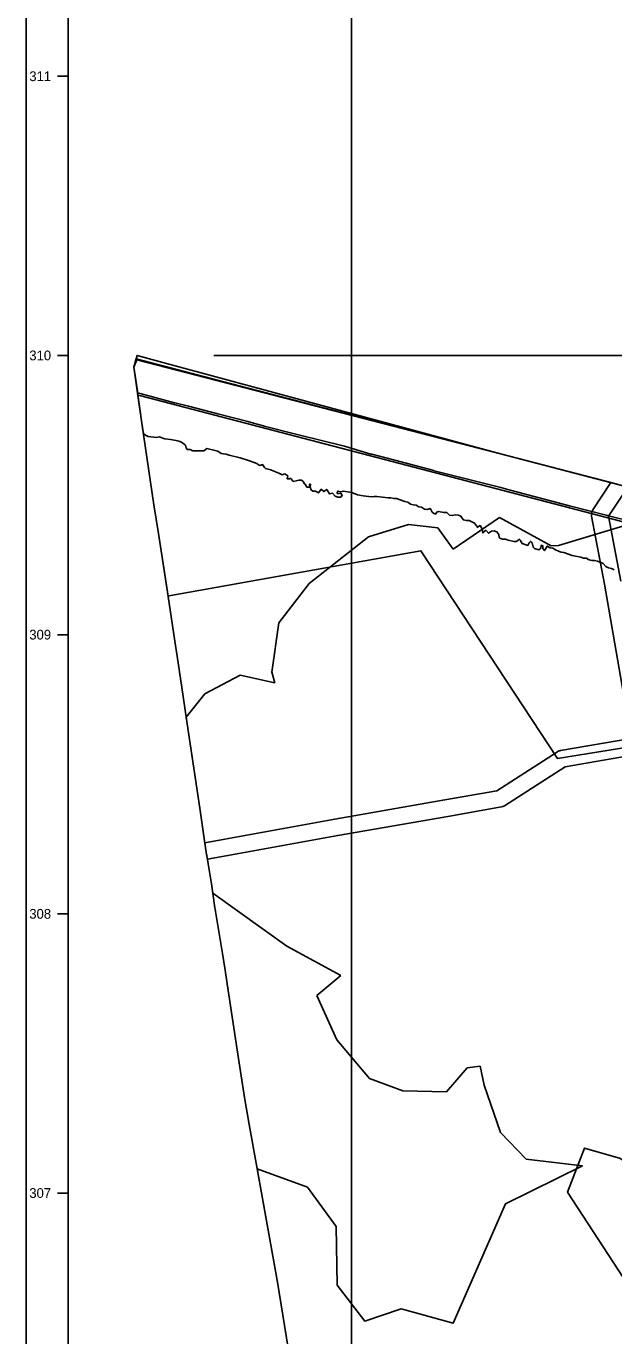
# Model space of a CAD drawing. Extents: x 468834 to 503362, y 294936 to 320859.
# Drawn here: x 468834 to 470940, y 306489 to 311179 of the extents above; entities that cross this region are included whole.
import ezdxf

# ---------------------------------------------------------------- set-up
doc = ezdxf.new("R2010")
doc.units = 0
for name, color, linetype in [('1020108_TIN18_Kemeru_nacionala_parka_teritorija', 7, 'Continuous'), ('1020109_TIN19_Auto satiksmes radīto trokšņu robežlieluma pārsnieguma teritorija', 7, 'Continuous'), ('1020700_TIN7_nacionalas_un_vietejas_nozimes_infrastrukturas_attistibas_teritorijas', 7, 'Continuous'), ('7311080102_vides un dabas resursu aizsardzības aizsargjoslas teritorija ap purvu ar platību lielāku par 100 hektāriem', 7, 'Continuous'), ('7312030301_ekspluatācijas aizsargjoslas teritorija gar valsts galvenajiem autoceļiem lauku apvidos', 7, 'Continuous'), ('7312050102_ekspluatācijas aizsargjoslas teritorija gar elektrisko tīklu gaisvadu līniju ārpus pilsētām un ciemiem ar nominālo spriegumu 110 kilovolti', 7, 'Continuous'), ('7313020300_nacionālā parka dabas lieguma zonas teritorija', 7, 'Continuous'), ('7313020500_nacionālā parka ainavu aizsardzības zonas teritorija', 7, 'Continuous'), ('7313080100_aizsargājamo ģeoloģisko un ģeomorfoloģisko dabas pieminekļu teritorija', 7, 'Continuous'), ('Nacionālā parka robeža', 7, 'Continuous'), ('ramis', 7, 'Continuous')]:
    doc.layers.add(name, color=color, linetype=linetype)

msp = doc.modelspace()

# ---------------------------------------------------------------- linework, layer by layer
at = {"layer": '1020108_TIN18_Kemeru_nacionala_parka_teritorija'}
for p, q in [((469227.8, 309987.6), (469220, 309957.6)), ((469220, 309957.6), (469225.4, 309920)), ((469569.4, 309898.4), (469227.8, 309987.6)), ((469225.4, 309920), (469234.5, 309856.3)), ((469858, 309823.5), (469569.4, 309898.4)), ((469234.5, 309856.3), (469248.7, 309758)), ((469974.3, 309793.4), (469858, 309823.5)), ((470533.7, 309647.7), (469974.3, 309793.4)), ((469248.7, 309758), (469291.8, 309464.8)), ((471174, 309480.9), (470533.7, 309647.7)), ((469291.8, 309464.8), (469307.5, 309362.6)), ((469307.5, 309362.6), (469342.9, 309136.4)), ((469342.9, 309136.4), (469366.7, 308976.5)), ((469366.7, 308976.5), (469374.5, 308922.5)), ((469374.5, 308922.5), (469391.1, 308811.1)), ((469391.1, 308811.1), (469414.2, 308656.3)), ((469414.2, 308656.3), (469455.5, 308378.7)), ((469455.5, 308378.7), (469476.6, 308236.6)), ((469476.6, 308236.6), (469480.2, 308212.7)), ((469480.2, 308212.7), (469480.8, 308209.1)), ((469480.8, 308209.1), (469485.6, 308178.9)), ((469485.6, 308178.9), (469497.3, 308108)), ((469497.3, 308108), (469510.3, 308021.9)), ((469510.3, 308021.9), (469511.2, 308016.3)), ((469511.2, 308016.3), (469512.4, 308008.1)), ((469512.4, 308008.1), (469537.6, 307858.5)), ((469537.6, 307858.5), (469546.8, 307797.9)), ((469546.8, 307797.9), (469554.1, 307750)), ((469554.1, 307750), (469589.5, 307512.8)), ((469589.5, 307512.8), (469616.2, 307342.4)), ((469616.2, 307342.4), (469633.3, 307245.2)), ((469633.3, 307245.2), (469660.7, 307093.4)), ((469660.7, 307093.4), (469734.9, 306680.4)), ((469734.9, 306680.4), (469772.2, 306444))]:
    msp.add_line(p, q, dxfattribs=at)
at = {"layer": '1020109_TIN19_Auto satiksmes radīto trokšņu robežlieluma pārsnieguma teritorija'}
msp.add_line((470853.8, 309564.3), (470533.7, 309647.7), dxfattribs=at)
for points in [[(469569.4, 309898.4), (469227.8, 309987.6), (469220, 309957.6), (469225.4, 309920), (469248.7, 309758), (469254.4, 309719.2)], [(470533.7, 309647.7), (470254, 309720.6), (469974.3, 309793.4), (469858.1, 309823.5), (469569.4, 309898.4)], [(469254.4, 309719.2), (469256.1, 309718.6), (469260.9, 309714.5), (469270.9, 309709.9), (469300.9, 309706.6), (469310.9, 309708.7), (469330.9, 309701.3), (469350.9, 309699.5), (469370.9, 309695.4), (469380.9, 309693), (469390.9, 309689.4), (469404.4, 309678.6), (469407.1, 309668.6), (469410.9, 309663.4), (469420.9, 309662.7), (469430.9, 309658.1), (469470.9, 309658.3), (469480.9, 309666.9), (469510.9, 309660.1), (469520.9, 309657), (469532.2, 309648.6), (469540.9, 309647.1), (469550.9, 309646.7), (469560.9, 309643.3), (469600.9, 309633.5), (469630.9, 309624), (469650.9, 309617.1), (469660.9, 309612.6), (469665.8, 309608.6), (469670.9, 309606), (469680.9, 309608.9), (469687.6, 309598.6), (469690.9, 309595.1), (469710.9, 309590.2), (469720.9, 309585.4), (469739.2, 309578.6), (469750.9, 309572.2), (469760.9, 309575.8), (469771.9, 309568.6), (469769.2, 309558.6), (469770.9, 309557.6), (469777.3, 309558.6), (469780.9, 309560.5), (469783.4, 309558.6), (469790.9, 309548.7), (469800.9, 309550.7), (469810.9, 309553.9), (469820.9, 309552.9), (469826.2, 309548.6), (469830.9, 309539.8), (469833, 309538.6), (469839.6, 309528.6), (469840.9, 309527.9), (469849.9, 309528.6), (469848.6, 309538.6), (469850.9, 309539.5), (469852.1, 309538.6), (469851.1, 309528.6), (469854.5, 309518.6), (469860.9, 309514), (469870.9, 309514.3), (469880.9, 309507.8), (469890.9, 309520.7), (469900.9, 309512.6), (469910.9, 309520.1), (469920.9, 309503.9), (469930.9, 309506.3), (469940.9, 309495.8), (469950.9, 309492.3), (469960.9, 309493), (469966.1, 309498.6), (469960.9, 309507), (469950.9, 309505), (469948.2, 309508.6), (469950.9, 309514.2), (469960.9, 309511), (469970.9, 309514.3), (470000.9, 309509.3), (470020.9, 309500.4), (470040.9, 309497.5), (470070.9, 309494.2), (470080.9, 309494.9), (470090.9, 309494.5), (470130.9, 309489.5), (470140.9, 309489.7), (470150.9, 309487.8), (470160.9, 309488), (470190.9, 309476.9), (470200.9, 309474.4), (470210.9, 309468), (470220.9, 309464.5), (470230.9, 309463.7), (470240.9, 309458.1), (470250.9, 309456.1), (470260.9, 309449.6), (470270.9, 309448.6), (470280.9, 309452), (470283.6, 309448.6), (470288.6, 309438.6), (470290.9, 309436.8), (470300.9, 309432), (470304.8, 309438.6), (470310.9, 309440.6), (470330.9, 309437.8), (470340.9, 309437.4), (470350.9, 309427.6), (470360.9, 309426.5), (470370.9, 309428.9), (470383.4, 309428.6), (470390.9, 309424.6), (470394.6, 309418.6), (470400.9, 309410.9), (470410.9, 309408.6), (470420.9, 309409), (470440.9, 309399.4), (470450.9, 309384.5), (470460.9, 309390.7), (470467.7, 309378.6), (470469.5, 309368.6), (470470.9, 309364.7), (470473.9, 309368.6), (470480.9, 309374.2), (470490.9, 309363.5), (470500.9, 309370.4), (470510.9, 309372.1), (470520.9, 309367.8), (470528.1, 309358.6), (470528.8, 309348.6), (470530.9, 309346), (470540.9, 309341.8), (470550.9, 309342.2), (470560.9, 309338.3), (470580.9, 309334.2), (470590.9, 309333.9), (470597.4, 309338.6), (470600.9, 309342.4), (470604.5, 309338.6), (470610.9, 309326.2), (470630.9, 309319.9), (470636.2, 309328.6), (470640.9, 309333.8), (470647.3, 309328.6), (470650.9, 309313.2), (470655.7, 309308.6), (470670.9, 309303.8), (470676.4, 309308.6), (470680.9, 309320.5), (470684.7, 309318.6), (470685, 309308.6), (470690.9, 309300.9), (470696.5, 309308.6), (470700.9, 309317.3), (470710.9, 309311.1), (470720.9, 309310.4), (470730.9, 309303.7), (470741.4, 309298.6), (470750.9, 309295.2), (470760.9, 309293.9), (470790.9, 309284), (470820.9, 309277.4), (470830.9, 309273.8), (470840.9, 309274.4), (470850.9, 309268.5), (470860.9, 309266.2), (470870.9, 309265.4), (470880.9, 309263.3), (470900.9, 309255), (470910.9, 309244.1), (470920.9, 309239.2), (470930.9, 309237.3), (470940.9, 309232.8)], [(471294, 309449.5), (471174, 309481), (470853.8, 309564.3)]]:
    msp.add_lwpolyline(points, dxfattribs=at)
at = {"layer": '1020700_TIN7_nacionalas_un_vietejas_nozimes_infrastrukturas_attistibas_teritorijas'}
for p, q in [((469234.3, 309857.9), (469245.1, 309855)), ((469234.3, 309857.9), (469245.1, 309855)), ((469245.1, 309855), (471074.1, 309377.1)), ((469245.1, 309855), (471074.1, 309377.1)), ((471657.5, 309353.9), (470533.9, 309648)), ((471657.5, 309353.9), (470533.9, 309648))]:
    msp.add_line(p, q, dxfattribs=at)
msp.add_lwpolyline([(470533.9, 309648), (469230.7, 309984.4), (469220, 309957.6), (469234.3, 309857.9)], dxfattribs=at)
msp.add_lwpolyline([(470533.9, 309648), (469230.7, 309984.4), (469220, 309957.6), (469234.3, 309857.9)], dxfattribs=at)
at = {"layer": '7311080102_vides un dabas resursu aizsardzības aizsargjoslas teritorija ap purvu ar platību lielāku par 100 hektāriem'}
for p, q in [((470203.3, 309394.9), (470060.3, 309350)), ((470309.5, 309382.6), (470203.3, 309394.9)), ((470529.5, 309419.7), (470363.4, 309306.7)), ((470714.5, 309317.9), (470529.5, 309419.7)), ((471026.5, 309405), (470741.4, 309319.8)), ((470060.3, 309350), (469847.5, 309183.2)), ((470363.4, 309306.7), (470309.5, 309382.6)), ((470741.4, 309319.8), (470714.5, 309317.9)), ((469847.5, 309183.2), (469738.9, 309042.3)), ((469738.9, 309042.3), (469714.3, 308866)), ((469600.4, 308854.6), (469473.8, 308788.6)), ((469724.4, 308827), (469600.4, 308854.6)), ((469714.3, 308866), (469724.4, 308827)), ((469473.8, 308788.6), (469407, 308704.6)), ((469407, 308704.6), (469414.2, 308656.3)), ((469414.2, 308656.3), (469455.5, 308378.7)), ((469455.5, 308378.7), (469476.6, 308236.6)), ((469476.6, 308236.6), (469480.2, 308212.7)), ((469480.2, 308212.7), (469480.8, 308209.1)), ((469480.8, 308209.1), (469485.6, 308178.9)), ((469485.6, 308178.9), (469497.3, 308108)), ((469497.3, 308108), (469502.5, 308073.9)), ((469502.5, 308073.9), (469768.2, 307884.2)), ((469768.2, 307884.2), (469961.7, 307778.9)), ((469961.7, 307778.9), (469875.3, 307707.4)), ((469875.3, 307707.4), (469946.7, 307548.6)), ((469946.7, 307548.6), (470064.5, 307410)), ((470339.6, 307363.1), (470414.3, 307449.1)), ((470414.3, 307449.1), (470460.4, 307454.3)), ((470460.4, 307454.3), (470474.7, 307386.8)), ((470064.5, 307410), (470183.2, 307366.1)), ((470474.7, 307386.8), (470533.8, 307217)), ((470183.2, 307366.1), (470339.6, 307363.1)), ((470533.8, 307217), (470626, 307120.9)), ((470626, 307120.9), (470827.8, 307097.9)), ((469661.9, 307086.9), (469734.9, 306680.4)), ((469734.9, 306680.4), (469772.2, 306444))]:
    msp.add_line(p, q, dxfattribs=at)
msp.add_lwpolyline([(470827.8, 307097.9), (470551.6, 306961.9), (470364.1, 306533.5), (470177.2, 306585.9), (470047.1, 306540.7), (469948.5, 306670.1), (469944.2, 306880.5), (469841.8, 307021.4), (469661.9, 307086.9)], dxfattribs=at)
at = {"layer": '7312030301_ekspluatācijas aizsargjoslas teritorija gar valsts galvenajiem autoceļiem lauku apvidos'}
msp.add_lwpolyline([(471012.2, 309402.5), (470920.5, 309425.9), (470912.7, 309427.9), (470780.4, 309461.9), (470568.6, 309517.8), (470534.4, 309526.8), (470296.1, 309587.3), (470295, 309587.6), (470154.6, 309624.9), (470072.1, 309646.2), (470069.2, 309647), (469974, 309674.7), (469809.8, 309715.5), (469809.2, 309715.7), (469686.1, 309747.3), (469684.3, 309747.8), (469648.5, 309757.6), (469628.4, 309762.9), (469520.6, 309791), (469415, 309818.2), (469366.2, 309830.4), (469364.8, 309830.8), (469286, 309851.8), (469233.2, 309865.6), (469232.3, 309872), (469225.4, 309920), (469220, 309957.6), (469231, 310000.2), (469323.5, 309975.2), (470233.6, 309729.2), (470533.9, 309648), (470928.4, 309544.5), (470989.6, 309528.5)], dxfattribs=at)
at = {"layer": '7312050102_ekspluatācijas aizsargjoslas teritorija gar elektrisko tīklu gaisvadu līniju ārpus pilsētām un ciemiem ar nominālo spriegumu 110 kilovolti'}
for points in [[(470974.1, 308787.5), (470905.8, 309181.3), (470859.9, 309424.7), (470859.4, 309430.4), (470860, 309436.1), (470861.7, 309441.6), (470864.3, 309446.7), (470928.5, 309544.7), (470989.7, 309528.7), (470921.1, 309423.9), (470964.8, 309192.2)], [(471040.4, 308574.1), (470764.8, 308527.1), (470547.7, 308387.3), (470542.3, 308384.6), (470536.6, 308383), (470344.2, 308349.2), (469950.1, 308280.7), (469556.8, 308208.6), (469483, 308195.4), (469480.2, 308212.7), (469473.9, 308254.7), (469473.9, 308254.8), (469546.1, 308267.6), (469939.5, 308339.7), (470333.8, 308408.3), (470520.3, 308441.1), (470737.5, 308580.8), (470740.3, 308582.2), (470742.7, 308583.5), (470745.7, 308584.4), (470748.4, 308585.1), (471000.9, 308628.3)]]:
    msp.add_lwpolyline(points, dxfattribs=at)
at = {"layer": '7313020300_nacionālā parka dabas lieguma zonas teritorija'}
for p, q in [((469342.6, 309138.4), (469342.9, 309136.4)), ((469342.9, 309136.4), (469366.7, 308976.5)), ((469366.7, 308976.5), (469374.5, 308922.5)), ((469374.5, 308922.5), (469391.1, 308811.1)), ((469391.1, 308811.1), (469414.2, 308656.3)), ((469414.2, 308656.3), (469455.5, 308378.7)), ((469455.5, 308378.7), (469476.6, 308236.6)), ((469476.6, 308236.6), (469480.2, 308212.7)), ((469480.2, 308212.7), (469480.8, 308209.1)), ((469480.8, 308209.1), (469485.6, 308178.9)), ((469485.6, 308178.9), (469497.3, 308108)), ((469497.3, 308108), (469510.3, 308021.9)), ((469510.3, 308021.9), (469511.2, 308016.3)), ((469511.2, 308016.3), (469512.4, 308008.1)), ((469512.4, 308008.1), (469537.6, 307858.5)), ((469537.6, 307858.5), (469546.8, 307797.9)), ((469546.8, 307797.9), (469554.1, 307750)), ((469554.1, 307750), (469589.5, 307512.8)), ((469589.5, 307512.8), (469616.2, 307342.4)), ((469616.2, 307342.4), (469633.3, 307245.2)), ((469633.3, 307245.2), (469660.7, 307093.4)), ((469660.7, 307093.4), (469734.9, 306680.4)), ((469734.9, 306680.4), (469772.2, 306444))]:
    msp.add_line(p, q, dxfattribs=at)
msp.add_lwpolyline([(473629.2, 309022.5), (473500.8, 309001.6), (473371, 308980.6), (473056, 308930.1), (472984.9, 308919), (472947.1, 308913.1), (472780.3, 308887.2), (472670.2, 308868.4), (472607.3, 308857.7), (472596.1, 308855.8), (472585.6, 308854), (472586.6, 308843.7), (472583.8, 308821.6), (472580.6, 308795.8), (472561, 308803.7), (472489.5, 308831.8), (472473.4, 308838.1), (472468.7, 308837.4), (471485.7, 308676.5), (470737.3, 308556.5), (470248.3, 309300.7), (469351.9, 309139.9), (469342.6, 309138.4)], dxfattribs=at)
at = {"layer": '7313020500_nacionālā parka ainavu aizsardzības zonas teritorija'}
for p, q in [((469227.8, 309987.6), (469220, 309957.6)), ((469220, 309957.6), (469225.4, 309920)), ((469569.4, 309898.4), (469227.8, 309987.6)), ((469225.4, 309920), (469234.5, 309856.3)), ((469858, 309823.5), (469569.4, 309898.4)), ((469234.5, 309856.3), (469248.7, 309758)), ((469974.3, 309793.4), (469858, 309823.5)), ((470533.7, 309647.7), (469974.3, 309793.4)), ((469248.7, 309758), (469291.8, 309464.8)), ((471174, 309480.9), (470533.7, 309647.7)), ((469291.8, 309464.8), (469307.5, 309362.6)), ((469307.5, 309362.6), (469342.6, 309138.4)), ((470248.3, 309300.7), (470737.3, 308556.5))]:
    msp.add_line(p, q, dxfattribs=at)
for points in [[(469342.6, 309138.4), (469351.9, 309139.9), (470248.3, 309300.7)], [(470737.3, 308556.5), (471485.7, 308676.5), (472468.7, 308837.4)]]:
    msp.add_lwpolyline(points, dxfattribs=at)
at = {"layer": '7313080100_aizsargājamo ģeoloģisko un ģeomorfoloģisko dabas pieminekļu teritorija'}
msp.add_lwpolyline([(471793.1, 305842.4), (471329.7, 306756.6), (471146.8, 306973.4), (470963.4, 307124.4), (470835.1, 307161.1), (470773.7, 307003.7), (471558.2, 305800.8)], dxfattribs=at)
at = {"layer": 'Nacionālā parka robeža'}
for p, q in [((469227.8, 309987.6), (469220, 309957.6)), ((469220, 309957.6), (469225.4, 309920)), ((469569.4, 309898.4), (469227.8, 309987.6)), ((469225.4, 309920), (469234.5, 309856.3)), ((469858, 309823.5), (469569.4, 309898.4)), ((469234.5, 309856.3), (469248.7, 309758)), ((469974.3, 309793.4), (469858, 309823.5)), ((470533.7, 309647.7), (469974.3, 309793.4)), ((469248.7, 309758), (469291.8, 309464.8)), ((471174, 309480.9), (470533.7, 309647.7)), ((469291.8, 309464.8), (469307.5, 309362.6)), ((469307.5, 309362.6), (469342.9, 309136.4)), ((469342.9, 309136.4), (469366.7, 308976.5)), ((469366.7, 308976.5), (469374.5, 308922.5)), ((469374.5, 308922.5), (469391.1, 308811.1)), ((469391.1, 308811.1), (469414.2, 308656.3)), ((469414.2, 308656.3), (469455.5, 308378.7)), ((469455.5, 308378.7), (469476.6, 308236.6)), ((469476.6, 308236.6), (469480.2, 308212.7)), ((469480.2, 308212.7), (469480.8, 308209.1)), ((469480.8, 308209.1), (469485.6, 308178.9)), ((469485.6, 308178.9), (469497.3, 308108)), ((469497.3, 308108), (469510.3, 308021.9)), ((469510.3, 308021.9), (469511.2, 308016.3)), ((469511.2, 308016.3), (469512.4, 308008.1)), ((469512.4, 308008.1), (469537.6, 307858.5)), ((469537.6, 307858.5), (469546.8, 307797.9)), ((469546.8, 307797.9), (469554.1, 307750)), ((469554.1, 307750), (469589.5, 307512.8)), ((469589.5, 307512.8), (469616.2, 307342.4)), ((469616.2, 307342.4), (469633.3, 307245.2)), ((469633.3, 307245.2), (469660.7, 307093.4)), ((469660.7, 307093.4), (469734.9, 306680.4)), ((469734.9, 306680.4), (469772.2, 306444))]:
    msp.add_line(p, q, dxfattribs=at)
at = {"layer": 'ramis'}
for p, q in [((468983.8, 295086.2), (468983.8, 316660.3)), ((470000, 304835), (470000, 312492.9)), ((468983.8, 311000), (468945.7, 311000)), ((468983.8, 310000), (468945.7, 310000)), ((469506.5, 310000), (500923.3, 310000)), ((468983.8, 309000), (468945.7, 309000)), ((468983.8, 308000), (468945.7, 308000)), ((468983.8, 307000), (468945.7, 307000))]:
    msp.add_line(p, q, dxfattribs=at)
msp.add_lwpolyline([(501073.3, 316810.3), (468833.8, 316810.3), (468833.8, 294936.2), (501073.3, 294936.2)], close=True, dxfattribs=at)

# ---------------------------------------------------------------- texts
for s, p in [('311', (468845, 310982.6)), ('310', (468845, 309982.6)), ('309', (468845, 308982.6)), ('308', (468845, 307982.6)), ('307', (468845, 306982.6))]:
    msp.add_text(s, height=35, dxfattribs=at).set_placement(p)

doc.saveas('drawing.dxf')
